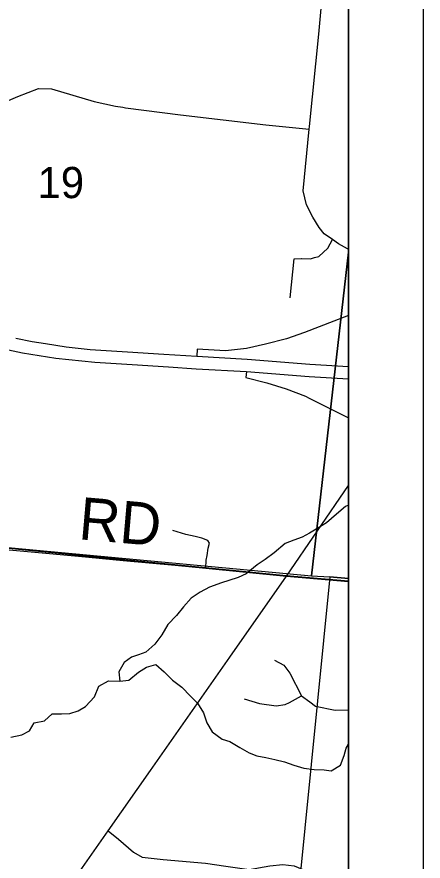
# Model space of a CAD drawing. Extents: x 0 to 34, y 0 to 22.
# Drawn here: x 8.456 to 9, y 19.591 to 20.723 of the extents above; entities that cross this region are included whole.
import ezdxf

# ---------------------------------------------------------------- set-up
doc = ezdxf.new("R2010")
doc.units = 0
for name, color, linetype in [('Default', 7, 'Continuous'), ('GM_X_County_Road', 7, 'Continuous'), ('GM_X_Interchange_Ramps', 7, 'Continuous'), ('GM_X_Minor_River', 7, 'Continuous'), ('GM_X_Section', 7, 'Continuous'), ('GM_X_Section_Text', 7, 'Continuous'), ('GM_X_State_Route', 7, 'Continuous'), ('GM_X_Township_Road', 7, 'Continuous'), ('GM_X_Township_Road_Text', 7, 'Continuous'), ('SH_Cut_Line', 7, 'Continuous'), ('SH_Data', 7, 'Continuous')]:
    doc.layers.add(name, color=color, linetype=linetype)

msp = doc.modelspace()

# ---------------------------------------------------------------- linework, layer by layer
at = {"layer": 'Default'}
for points in [[(8.9, 20.4078), (8.9, 20.9), (7.9386, 20.9), (7.855, 20.0664), (7.8637, 20.0659), (8.8506, 19.9738)], [(8.9, 19.9702), (8.9, 20.4078), (8.8506, 19.9738), (8.8752, 19.9725)], [(8.9, 19.0188), (8.9, 19.9702), (8.8752, 19.9725), (8.7834, 19.051)]]:
    msp.add_lwpolyline(points, close=True, dxfattribs=at)
at = {"layer": 'GM_X_County_Road'}
msp.add_line((8.8168, 19.9732), (8.9, 20.095), dxfattribs=at)
for points in [[(8.9, 20.4118), (8.8985, 20.4123), (8.8866, 20.4188), (8.8784, 20.4246), (8.8673, 20.4324), (8.8609, 20.4408), (8.8524, 20.4545), (8.8439, 20.471), (8.8392, 20.4902), (8.8473, 20.5728), (8.8478, 20.5761), (8.8601, 20.7003), (8.8746, 20.8589), (8.8785, 20.9)], [(8.6345, 19.7128), (8.7408, 19.8647), (8.8168, 19.9732)], [(8.5308, 19.5646), (8.5777, 19.6316), (8.6345, 19.7128)]]:
    msp.add_lwpolyline(points, dxfattribs=at)
at = {"layer": 'GM_X_Interchange_Ramps'}
msp.add_line((8.8473, 20.212), (8.9, 20.1857), dxfattribs=at)
for points in [[(8.9, 20.3227), (8.8412, 20.2998), (8.8171, 20.2916), (8.7888, 20.2842), (8.7635, 20.2787), (8.7351, 20.2756), (8.6971, 20.2776), (8.6965, 20.2681)], [(8.7632, 20.2476), (8.7622, 20.2398), (8.7906, 20.2324), (8.8165, 20.2244), (8.8424, 20.2145), (8.8473, 20.212)]]:
    msp.add_lwpolyline(points, dxfattribs=at)
at = {"layer": 'GM_X_Minor_River'}
for points in [[(8.9, 20.0683), (8.8959, 20.0665), (8.8839, 20.0562), (8.8707, 20.0447), (8.8591, 20.0374), (8.8479, 20.0309), (8.8379, 20.0254), (8.8268, 20.0215), (8.8149, 20.0169), (8.8005, 20.0043), (8.7881, 19.9955), (8.7777, 19.9882), (8.763, 19.9764), (8.7522, 19.9713), (8.7396, 19.9675), (8.7296, 19.9643), (8.7135, 19.9586), (8.7012, 19.9517), (8.6892, 19.9437), (8.6787, 19.9322), (8.6696, 19.9206), (8.6579, 19.9083), (8.65, 19.8945), (8.6406, 19.8822), (8.6285, 19.8711), (8.6185, 19.8675), (8.609, 19.8644), (8.5993, 19.8574), (8.5921, 19.845), (8.5937, 19.8324), (8.6055, 19.8337), (8.6183, 19.8444), (8.6292, 19.8513), (8.6418, 19.8548), (8.6529, 19.845), (8.664, 19.8337), (8.6767, 19.8242), (8.6882, 19.8122), (8.6978, 19.8028), (8.7055, 19.7901), (8.7101, 19.7763), (8.7174, 19.7643), (8.7308, 19.7544), (8.741, 19.7515), (8.7544, 19.7436), (8.7668, 19.7364), (8.7773, 19.7323), (8.7891, 19.7301), (8.8011, 19.7272), (8.814, 19.7242), (8.8268, 19.7197), (8.8403, 19.7155), (8.854, 19.714), (8.8673, 19.7133), (8.8767, 19.7123), (8.8891, 19.7196), (8.894, 19.7328), (8.8969, 19.7426), (8.9, 19.748)], [(8.4475, 19.7575), (8.462, 19.7605), (8.4724, 19.7656), (8.4787, 19.7764), (8.4925, 19.7791), (8.5026, 19.7884), (8.5151, 19.7884), (8.5265, 19.7889), (8.5377, 19.7928), (8.5477, 19.7983), (8.5594, 19.8113), (8.5655, 19.8259), (8.5782, 19.8328), (8.5937, 19.8324)]]:
    msp.add_lwpolyline(points, dxfattribs=at)
at = {"layer": 'GM_X_Section'}
msp.add_lwpolyline([(7.8637, 20.0659), (8.8506, 19.9738), (8.8752, 19.9725), (8.7834, 19.051), (7.7938, 19.1583)], close=True, dxfattribs=at)
at = {"layer": 'GM_X_State_Route'}
for points in [[(7.9727, 20.4605), (7.9756, 20.4597), (8.0147, 20.4479), (8.042, 20.4387), (8.0726, 20.4268), (8.1055, 20.413), (8.1615, 20.387), (8.2159, 20.362), (8.2674, 20.3382), (8.3047, 20.3216), (8.3483, 20.3045), (8.3876, 20.2915), (8.4273, 20.2803), (8.463, 20.2729), (8.5077, 20.2655), (8.5599, 20.2604), (8.61, 20.2571), (8.6586, 20.254), (8.6956, 20.2515), (8.7632, 20.2476), (8.8472, 20.2411), (8.9, 20.2377)], [(8.4539, 20.2923), (8.476, 20.2878), (8.4937, 20.2852), (8.5217, 20.2809), (8.5537, 20.2774), (8.6039, 20.2741), (8.6524, 20.271), (8.6965, 20.2681), (8.7642, 20.2642), (8.8482, 20.2577), (8.9, 20.2543)]]:
    msp.add_lwpolyline(points, dxfattribs=at)
at = {"layer": 'GM_X_Township_Road'}
for p, q in [((8.5382, 19.9999), (8.5979, 19.9944)), ((8.8168, 19.9732), (8.9, 19.9662)), ((8.8207, 19.804), (8.8368, 19.8127))]:
    msp.add_line(p, q, dxfattribs=at)
for points in [[(6.4945, 20.1803), (6.6784, 20.1674), (6.71, 20.1637), (6.7526, 20.1604), (6.7658, 20.1595), (6.8112, 20.1567), (6.8137, 20.1565), (6.8473, 20.1572), (6.8656, 20.1588), (6.8864, 20.1589), (6.9284, 20.155), (7.0596, 20.1449), (7.4148, 20.1115), (7.4871, 20.1047), (7.7604, 20.0801), (7.7765, 20.0797), (7.8238, 20.073), (7.9584, 20.0596), (8.6673, 19.9886), (8.7085, 19.9845), (8.8165, 19.9737), (8.9, 19.9667), (8.9, 20.9), (3.8479, 20.9)], [(8.3882, 20.5851), (8.4259, 20.6034), (8.4568, 20.6165), (8.4843, 20.6273), (8.5018, 20.6268), (8.5591, 20.6099), (8.5876, 20.6036), (8.5974, 20.602)], [(8.5974, 20.602), (8.6013, 20.6014), (8.6749, 20.5919), (8.7891, 20.5787), (8.8473, 20.5728)], [(8.8543, 20.4004), (8.8603, 20.402), (8.8725, 20.4129), (8.8784, 20.4246)], [(8.8216, 20.3467), (8.8271, 20.399), (8.8364, 20.3993)], [(8.8364, 20.3993), (8.8372, 20.3993), (8.8491, 20.399), (8.8543, 20.4004)], [(8.9, 14.8595), (8.9, 19.9667), (8.8165, 19.9737), (8.7085, 19.9845), (8.6673, 19.9886), (7.9584, 20.0596), (7.8238, 20.073), (7.7765, 20.0797), (7.7604, 20.0801), (7.4871, 20.1047), (7.4148, 20.1115), (7.0596, 20.1449), (6.9284, 20.155), (6.8864, 20.1589), (6.8656, 20.1588), (6.8473, 20.1572), (6.8137, 20.1565), (6.8112, 20.1567), (6.7658, 20.1595), (6.7526, 20.1604), (6.71, 20.1637), (6.6784, 20.1674), (6.4945, 20.1803)], [(8.7088, 19.984), (8.7093, 19.9946), (8.7104, 20.0011), (8.7117, 20.0108), (8.7138, 20.0174), (8.7113, 20.0212), (8.7035, 20.0241), (8.6945, 20.0263), (8.6819, 20.0289), (8.6646, 20.0346)], [(8.389, 20.0134), (8.4009, 20.0124), (8.5382, 19.9999)], [(8.5979, 19.9944), (8.6675, 19.9881), (8.7088, 19.984), (8.8168, 19.9732)], [(8.8007, 19.8607), (8.8133, 19.854), (8.8214, 19.8432), (8.8368, 19.8127), (8.848, 19.8046), (8.8557, 19.7987), (8.882, 19.7937), (8.9, 19.794)], [(8.7601, 19.8089), (8.7806, 19.8024), (8.8029, 19.7994), (8.8151, 19.801), (8.8207, 19.804)], [(8.5777, 19.6316), (8.5917, 19.6205), (8.6117, 19.603), (8.6233, 19.5965), (8.6518, 19.5933), (8.7083, 19.5881), (8.7355, 19.5843), (8.7667, 19.5799), (8.7947, 19.5848), (8.8119, 19.5866), (8.8273, 19.5848), (8.8494, 19.5754), (8.8788, 19.547)]]:
    msp.add_lwpolyline(points, dxfattribs=at)
at = {"layer": 'SH_Cut_Line'}
msp.add_lwpolyline([(8.9, 14.8595), (8.9, 20.9), (2.1, 20.9), (2.1, 19.3633)], dxfattribs=at)
at = {"layer": 'SH_Data'}
for p, q in [((9, 21), (9, 14)), ((8.9, 20.9), (8.9, 14.1))]:
    msp.add_line(p, q, dxfattribs=at)

# ---------------------------------------------------------------- texts
at = {"layer": 'GM_X_Section_Text'}
msp.add_text('19', height=0.04186, rotation=0, dxfattribs=at).set_placement((8.4833, 20.4802))
at = {"layer": 'GM_X_Township_Road_Text'}
msp.add_text('RD', height=0.05682, rotation=355.0725, dxfattribs=at).set_placement((8.5371, 20.0228))

doc.saveas('drawing.dxf')
